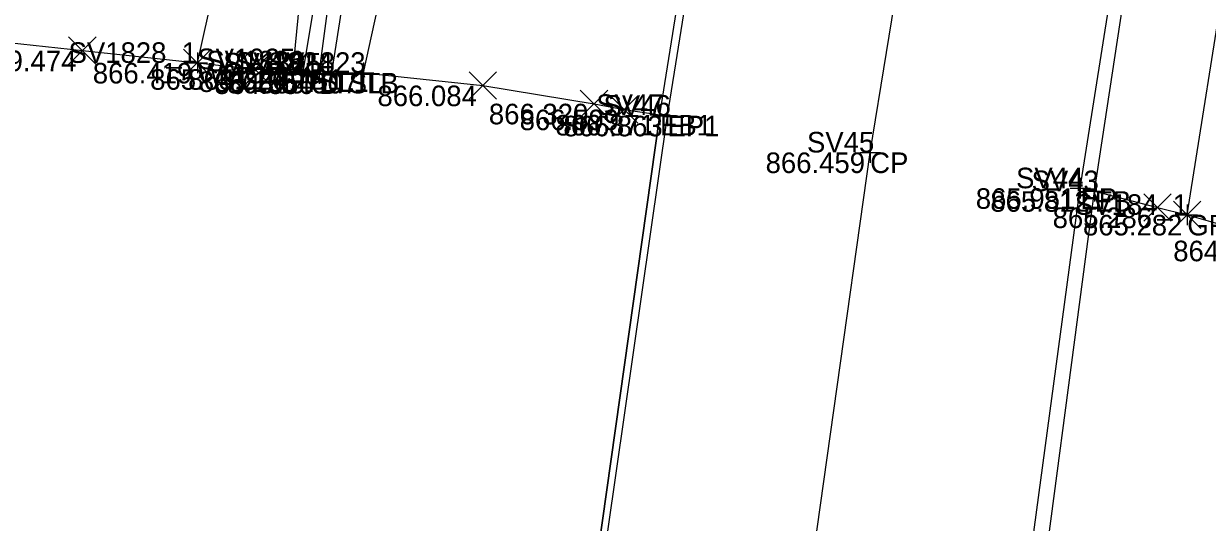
# Model space of a CAD drawing. Extents: x 2228183 to 2230895, y 679226 to 682223.
# Drawn here: x 2228233.8 to 2228291.3, y 680376.3 to 680400.5 of the extents above; entities that cross this region are included whole.
import ezdxf

# ---------------------------------------------------------------- set-up
doc = ezdxf.new("R2010")
doc.units = 0
for name, color, linetype in [('DR_X_Ditch', 7, 'Continuous'), ('PV_X_COP', 7, 'Continuous'), ('PV_X_EOP', 7, 'Continuous'), ('PV_X_Shoulder_Aggregate', 7, 'Continuous'), ('RD_X_GR_Rt', 7, 'Continuous'), ('SC_Scratch1', 7, 'Continuous'), ('SV_P_Control_Cells_Set', 7, 'Continuous'), ('SV_X_Random_Point', 7, 'Continuous'), ('SV_X_Shot_Marker', 7, 'Continuous'), ('SV_X_Terrain_Boundary', 7, 'Continuous'), ('SV_X_Text_Comment', 7, 'Continuous'), ('SV_X_Toe_of_Slope', 7, 'Continuous'), ('SV_X_Top_of_Bank', 7, 'Continuous'), ('VG_X_Tree_Line_Rt', 7, 'Continuous')]:
    doc.layers.add(name, color=color, linetype=linetype)

msp = doc.modelspace()

# ---------------------------------------------------------------- linework, layer by layer
at = {"layer": 'DR_X_Ditch'}
msp.add_line((2228248.152, 680398.096), (2228248.152, 680398.096), dxfattribs=at)
msp.add_lwpolyline([(2228248.152, 680398.096), (2228249.095, 680405.268), (2228249.691, 680412.267), (2228250.738, 680416.294), (2228251.182, 680418.776), (2228251.754, 680424.586), (2228252.425, 680433.411), (2228253.413, 680441.336), (2228254.696, 680448.568), (2228253.869, 680453.653), (2228253.021, 680456.333), (2228253.924, 680458.912), (2228254.395, 680462.481), (2228255.204, 680465.484), (2228255.304, 680468.353), (2228255.892, 680471.795), (2228254.699, 680480.343), (2228253.82, 680482.578)], dxfattribs=at)
at = {"layer": 'PV_X_COP'}
msp.add_lwpolyline([(2228262.604, 680193.524), (2228262.146, 680218.328), (2228262.437, 680243.717), (2228263.104, 680268.902), (2228264.443, 680294.535), (2228266.222, 680319.78), (2228268.589, 680344.685), (2228271.405, 680369.17), (2228274.939, 680394.252), (2228278.914, 680418.584), (2228283.486, 680443.605), (2228288.154, 680467.93), (2228293.014, 680492.349), (2228297.716, 680516.963), (2228302.55, 680541.357), (2228307.231, 680565.55), (2228311.972, 680589.697), (2228316.792, 680614.507), (2228321.818, 680639.234), (2228326.722, 680663.726), (2228331.754, 680688.345)], dxfattribs=at)
at = {"layer": 'PV_X_EOP'}
for points in [[(2228252.395, 680193.158), (2228252.017, 680217.928), (2228252.166, 680243.969), (2228252.969, 680269.118), (2228254.41, 680295.326), (2228256.289, 680320.959), (2228258.609, 680345.957), (2228261.353, 680370.084), (2228265.081, 680396.038), (2228268.964, 680420.227), (2228273.571, 680445.935), (2228278.026, 680470.103), (2228282.912, 680494.405), (2228287.764, 680519.213), (2228292.491, 680542.983), (2228297.123, 680567.244), (2228301.725, 680591.365), (2228306.593, 680616.395), (2228311.35, 680641.501), (2228316.271, 680666.166), (2228321.17, 680690.642)], [(2228272.958, 680193.788), (2228272.514, 680218.749), (2228272.761, 680243.66), (2228273.456, 680268.53), (2228274.726, 680293.686), (2228276.435, 680318.586), (2228278.817, 680343.424), (2228281.861, 680368.095), (2228285.158, 680392.512), (2228289.018, 680417.009), (2228293.5, 680441.465), (2228298.055, 680466.05), (2228302.846, 680490.329), (2228307.636, 680514.848), (2228312.366, 680539.332), (2228317.173, 680563.701), (2228322.066, 680588.07), (2228326.883, 680612.686), (2228331.837, 680637.002), (2228336.903, 680661.667), (2228341.796, 680685.984)]]:
    msp.add_lwpolyline(points, dxfattribs=at)
at = {"layer": 'PV_X_Shoulder_Aggregate'}
for points in [[(2228251.688, 680193.163), (2228251.4, 680217.895), (2228251.524, 680243.996), (2228252.468, 680269.192), (2228253.879, 680295.388), (2228256.006, 680320.988), (2228258.289, 680346.01), (2228261.054, 680370.168), (2228264.719, 680396.078), (2228268.579, 680420.338), (2228273.034, 680446.093), (2228277.679, 680470.182), (2228282.388, 680494.533), (2228287.18, 680519.364), (2228291.91, 680543.114), (2228296.422, 680567.366), (2228298.906, 680579.954), (2228299.502, 680580.4), (2228300.213, 680585.238), (2228301.248, 680591.351), (2228306.286, 680616.474), (2228310.79, 680641.597), (2228315.628, 680666.277), (2228320.418, 680690.758)], [(2228273.386, 680193.772), (2228272.957, 680218.691), (2228273.264, 680243.644), (2228274.133, 680268.478), (2228275.472, 680293.621), (2228277.239, 680318.511), (2228279.649, 680343.317), (2228282.622, 680367.988), (2228285.854, 680392.371), (2228289.575, 680416.853), (2228293.89, 680441.38), (2228298.61, 680465.949), (2228303.2, 680490.238), (2228308.065, 680514.741), (2228313.026, 680539.169), (2228317.996, 680563.53), (2228322.869, 680587.896), (2228327.71, 680612.549), (2228332.443, 680636.855), (2228337.368, 680661.526), (2228342.398, 680685.817)]]:
    msp.add_lwpolyline(points, dxfattribs=at)
at = {"layer": 'RD_X_GR_Rt'}
msp.add_lwpolyline([(2228290.359, 680391.22), (2228294.274, 680415.932), (2228298.414, 680440.801), (2228302.718, 680465.177), (2228307.188, 680489.321), (2228312.206, 680513.859), (2228316.706, 680538.587), (2228321.519, 680562.878), (2228326.574, 680587.113), (2228331.32, 680611.864), (2228336.079, 680636.156), (2228341.093, 680660.882), (2228346.244, 680685.06), (2228350.849, 680709.572), (2228355.751, 680733.95), (2228357.804, 680743.718), (2228360.585, 680755.706), (2228364.08, 680768.892), (2228368.125, 680781.145)], dxfattribs=at)
at = {"layer": 'SV_X_Random_Point'}
for p, q in [((2228235.964, 680398.537), (2228237.298, 680399.872)), ((2228235.964, 680399.872), (2228237.298, 680398.537)), ((2228241.557, 680397.941), (2228242.891, 680399.276)), ((2228241.557, 680399.276), (2228242.891, 680397.941)), ((2228244.344, 680397.635), (2228245.678, 680398.97)), ((2228244.344, 680398.97), (2228245.678, 680397.635)), ((2228255.436, 680396.838), (2228256.77, 680398.173)), ((2228255.436, 680398.173), (2228256.77, 680396.838)), ((2228260.845, 680395.954), (2228262.179, 680397.289)), ((2228260.845, 680397.289), (2228262.179, 680395.954)), ((2228262.313, 680395.67), (2228263.647, 680397.005)), ((2228262.313, 680397.005), (2228263.647, 680395.67)), ((2228288.249, 680390.911), (2228289.583, 680392.246)), ((2228288.249, 680392.246), (2228289.583, 680390.911)), ((2228289.692, 680390.553), (2228291.026, 680391.888)), ((2228289.692, 680391.888), (2228291.026, 680390.553))]:
    msp.add_line(p, q, dxfattribs=at)
at = {"layer": 'SV_X_Shot_Marker'}
for p, q in [((2228242.224, 680399.108), (2228242.224, 680398.108)), ((2228241.724, 680398.608), (2228242.724, 680398.608)), ((2228242.224, 680398.608), (2228242.224, 680398.608)), ((2228246.39, 680398.302), (2228247.39, 680398.302)), ((2228246.89, 680398.802), (2228246.89, 680397.802)), ((2228246.89, 680398.302), (2228246.89, 680398.302)), ((2228247.363, 680398.695), (2228247.363, 680397.695)), ((2228248.152, 680398.596), (2228248.152, 680397.596)), ((2228248.769, 680398.624), (2228248.769, 680397.624)), ((2228250.307, 680398.624), (2228250.307, 680397.624)), ((2228246.863, 680398.195), (2228247.863, 680398.195)), ((2228247.363, 680398.195), (2228247.363, 680398.195)), ((2228247.652, 680398.096), (2228248.652, 680398.096)), ((2228248.152, 680398.096), (2228248.152, 680398.096)), ((2228248.269, 680398.124), (2228249.269, 680398.124)), ((2228248.769, 680398.124), (2228248.769, 680398.124)), ((2228249.807, 680398.124), (2228250.807, 680398.124)), ((2228250.307, 680398.124), (2228250.307, 680398.124)), ((2228264.719, 680396.578), (2228264.719, 680395.578)), ((2228264.219, 680396.078), (2228265.219, 680396.078)), ((2228264.581, 680396.038), (2228265.581, 680396.038)), ((2228264.719, 680396.078), (2228264.719, 680396.078)), ((2228265.081, 680396.538), (2228265.081, 680395.538)), ((2228265.081, 680396.038), (2228265.081, 680396.038)), ((2228274.939, 680394.752), (2228274.939, 680393.752)), ((2228274.439, 680394.252), (2228275.439, 680394.252)), ((2228274.939, 680394.252), (2228274.939, 680394.252)), ((2228285.158, 680393.012), (2228285.158, 680392.012)), ((2228285.854, 680392.871), (2228285.854, 680391.871)), ((2228284.658, 680392.512), (2228285.658, 680392.512)), ((2228285.158, 680392.512), (2228285.158, 680392.512)), ((2228285.354, 680392.371), (2228286.354, 680392.371)), ((2228285.854, 680392.371), (2228285.854, 680392.371)), ((2228290.359, 680391.72), (2228290.359, 680390.72)), ((2228289.859, 680391.22), (2228290.859, 680391.22)), ((2228290.359, 680391.22), (2228290.359, 680391.22))]:
    msp.add_line(p, q, dxfattribs=at)
at = {"layer": 'SV_X_Terrain_Boundary'}
for points in [[(2228200.682, 680406.403), (2228209.65, 680403.669), (2228221.742, 680401.898), (2228226.631, 680400.787), (2228228.296, 680400.607), (2228232.417, 680399.658), (2228236.631, 680399.204), (2228242.224, 680398.608), (2228245.011, 680398.302), (2228246.89, 680398.302), (2228247.363, 680398.195), (2228248.152, 680398.096), (2228248.769, 680398.124), (2228250.307, 680398.124), (2228256.103, 680397.505), (2228261.512, 680396.621), (2228262.98, 680396.337), (2228264.719, 680396.078), (2228261.054, 680370.168)], [(2228282.622, 680367.988), (2228285.854, 680392.371), (2228288.916, 680391.578), (2228290.359, 680391.22), (2228294.777, 680389.962)]]:
    msp.add_lwpolyline(points, dxfattribs=at)
at = {"layer": 'SV_X_Toe_of_Slope'}
for p, q in [((2228247.363, 680398.195), (2228247.363, 680398.195)), ((2228248.769, 680398.124), (2228248.769, 680398.124))]:
    msp.add_line(p, q, dxfattribs=at)
for points in [[(2228247.363, 680398.195), (2228248.549, 680405.269), (2228248.818, 680412.227), (2228249.327, 680418.887), (2228250.556, 680424.555), (2228251.157, 680433.567), (2228252.542, 680441.162), (2228253.839, 680448.589), (2228253.231, 680453.1), (2228252.107, 680454.105), (2228250.987, 680456.203), (2228252.313, 680459.504), (2228253.331, 680462.687), (2228254.374, 680464.819), (2228254.89, 680468.476), (2228255.601, 680471.521), (2228254.065, 680480.323), (2228253.345, 680482.191)], [(2228248.769, 680398.124), (2228249.858, 680405.177), (2228250.692, 680412.274), (2228251.23, 680416.422), (2228252.326, 680418.965), (2228253.526, 680423.926), (2228253.811, 680432.797), (2228253.924, 680435.141), (2228254.135, 680441.28), (2228255.741, 680448.336), (2228254.458, 680453.857), (2228254.543, 680454.732), (2228254.934, 680456.198), (2228255.832, 680458.437), (2228255.885, 680462.309), (2228256.037, 680464.674), (2228255.856, 680468.365), (2228256.292, 680472.05), (2228254.247, 680482.064)]]:
    msp.add_lwpolyline(points, dxfattribs=at)
at = {"layer": 'SV_X_Top_of_Bank'}
msp.add_line((2228250.307, 680398.124), (2228250.307, 680398.124), dxfattribs=at)
for points in [[(2228250.307, 680398.124), (2228251.813, 680405.02), (2228252.399, 680412.097), (2228254.905, 680418.699), (2228255.946, 680423.789), (2228256.296, 680434.591), (2228257.527, 680440.797), (2228257.898, 680448.164), (2228256.801, 680454.49), (2228258.019, 680458.203), (2228257.686, 680462.292), (2228256.963, 680468.691), (2228257.054, 680472.414), (2228255.862, 680480.443), (2228255.026, 680481.727), (2228254.275, 680482.126)], [(2228246.89, 680398.302), (2228247.542, 680405.142), (2228248.019, 680412.274), (2228248.247, 680419.019), (2228247.645, 680424.706), (2228248.424, 680434.173), (2228248.473, 680441.514)]]:
    msp.add_lwpolyline(points, dxfattribs=at)
at = {"layer": 'VG_X_Tree_Line_Rt'}
msp.add_lwpolyline([(2228242.224, 680398.608), (2228254.757, 680454.617), (2228285.377, 680608.953), (2228295.459, 680686.843), (2228290.96, 680699.609), (2228297.38, 680721.363), (2228313.146, 680792.869)], dxfattribs=at)

# ---------------------------------------------------------------- texts
at = {"layer": 'SC_Scratch1'}
for s, p in [('869.474', (2228231.509, 680398.204)), ('866.419', (2228237.14, 680397.608)), ('866.419', (2228237.14, 680397.608)), ('865.641', (2228239.929, 680397.302)), ('865.320', (2228241.776, 680397.302)), ('865.165', (2228242.293, 680397.195)), ('864.856', (2228243.048, 680397.096)), ('865.046', (2228243.665, 680397.124)), ('865.507', (2228245.211, 680397.124)), ('866.084', (2228250.981, 680396.505)), ('866.320', (2228256.398, 680395.621)), ('866.599', (2228257.896, 680395.337)), ('866.871', (2228259.637, 680395.078)), ('866.863', (2228260.017, 680395.038)), ('866.459', (2228269.855, 680393.252)), ('865.951', (2228280.076, 680391.512)), ('865.812', (2228280.781, 680391.371)), ('865.286', (2228283.812, 680390.578)), ('865.282', (2228285.286, 680390.22)), ('865.282', (2228285.286, 680390.22)), ('864.408', (2228289.677, 680388.962))]:
    msp.add_text(s, height=1, dxfattribs=at).set_placement(p)
at = {"layer": 'SV_P_Control_Cells_Set'}
for s, p in [('SV1828_1', (2228235.961, 680398.608)), ('SV1925', (2228242.221, 680398.302)), ('SV1826', (2228242.661, 680398.195)), ('SV1825', (2228243.483, 680398.096)), ('SV1824', (2228244.049, 680398.124)), ('SV1823', (2228245.645, 680398.124)), ('SV47', (2228261.621, 680396.078)), ('SV46', (2228261.975, 680396.038)), ('SV45', (2228271.867, 680394.252)), ('SV44', (2228282.034, 680392.512)), ('SV43', (2228282.788, 680392.371)), ('SV184_1', (2228284.894, 680391.22))]:
    msp.add_text(s, height=1, dxfattribs=at).set_placement(p)
at = {"layer": 'SV_X_Text_Comment'}
for s, p in [('WOODSR', (2228242.224, 680397.608)), ('TB1', (2228246.89, 680397.302)), ('TSL1', (2228247.363, 680397.195)), ('D', (2228248.152, 680397.096)), ('TSL', (2228248.769, 680397.124)), ('TB', (2228250.307, 680397.124)), ('EB1', (2228264.719, 680395.078)), ('EP1', (2228265.081, 680395.038)), ('CP', (2228274.939, 680393.252)), ('EP', (2228285.158, 680391.512)), ('EB', (2228285.854, 680391.371)), ('GRRT2D', (2228290.359, 680390.22))]:
    msp.add_text(s, height=1, dxfattribs=at).set_placement(p)

doc.saveas('drawing.dxf')
